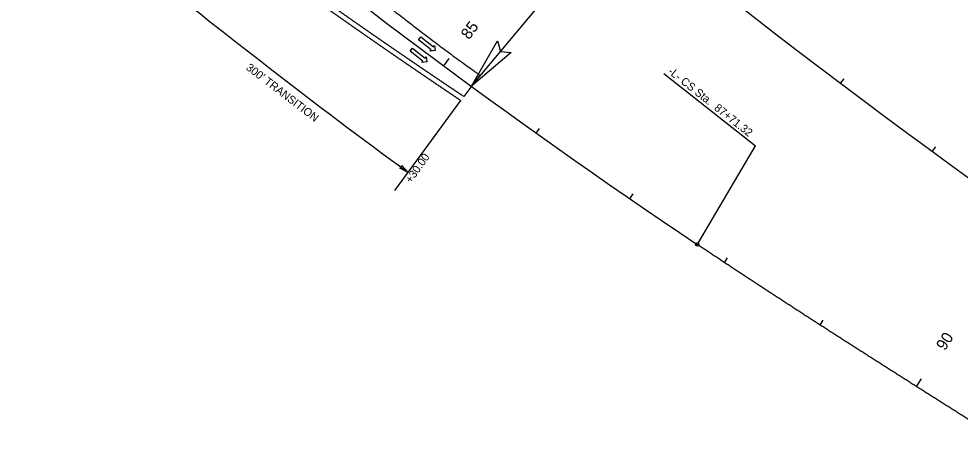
# Model space of a CAD drawing. Extents: x 1778969 to 1790720, y 807089 to 817794.
# Drawn here: x 1783038 to 1783861, y 811215 to 811575 of the extents above; entities that cross this region are included whole.
import ezdxf

# ---------------------------------------------------------------- set-up
doc = ezdxf.new("R2010")
doc.units = 0
for name, color, linetype in [('Prop Dimension', 7, 'Continuous'), ('Prop Dimension Text', 7, 'Continuous'), ('Prop EOT', 7, 'Continuous'), ('Prop Horizontal Alignment', 7, 'Continuous'), ('Prop Horizontal Alignment Station Label', 7, 'Continuous'), ('Prop Horizontal Alignment Tick Label', 7, 'Continuous'), ('Prop Horizontal Alignment Tick Large', 7, 'Continuous'), ('Prop Horizontal Alignment Tick Small', 7, 'Continuous'), ('Prop Lane Arrow CELL', 7, 'Continuous'), ('Prop Paved Shoulder', 7, 'Continuous'), ('Prop Terminator CELL', 7, 'Continuous')]:
    doc.layers.add(name, color=color, linetype=linetype)

msp = doc.modelspace()

# ---------------------------------------------------------------- linework, layer by layer
at = {"layer": 'Prop Dimension'}
msp.add_line((1783366.62, 811424.33), (1783424.41, 811503.2), dxfattribs=at)
msp.add_arc((1786819.89, 816137.48), 5823.1, 230.770165, 233.770165, dxfattribs=at)
at = {"layer": 'Prop EOT'}
msp.add_line((1783440.95, 811525.52), (1783427.01, 811506.75), dxfattribs=at)
msp.add_open_spline([(1782332.14, 812594.37), (1782340.74, 812583.67), (1782349.23, 812572.88), (1782357.82, 812562.17), (1782368.33, 812549.05), (1782378.92, 812535.99), (1782389.53, 812522.94), (1782400.47, 812509.49), (1782411.47, 812496.1), (1782422.5, 812482.73), (1782432.68, 812470.37), (1782442.88, 812458.04), (1782453.26, 812445.86), (1782464.11, 812433.14), (1782475.03, 812420.5), (1782485.99, 812407.88), (1782497.29, 812394.85), (1782508.62, 812381.84), (1782519.93, 812368.81), (1782530.42, 812356.73), (1782540.78, 812344.53), (1782551.36, 812332.52), (1782562.04, 812320.41), (1782573.16, 812308.69), (1782584.11, 812296.83), (1782595.68, 812284.29), (1782607.24, 812271.76), (1782618.83, 812259.26), (1782630.11, 812247.08), (1782641.41, 812234.93), (1782652.81, 812222.87), (1782664.21, 812210.82), (1782675.73, 812198.9), (1782687.17, 812186.89), (1782698.66, 812174.82), (1782710.02, 812162.63), (1782721.55, 812150.59), (1782732.97, 812138.66), (1782744.99, 812127.31), (1782756.58, 812115.53), (1782768.39, 812103.52), (1782779.79, 812091.1), (1782791.72, 812079.2), (1782803.99, 812066.97), (1782816.43, 812054.92), (1782828.91, 812042.91), (1782840.93, 812031.35), (1782852.92, 812019.75), (1782865.05, 812008.31), (1782876.51, 811997.51), (1782888.04, 811986.79), (1782899.51, 811976.02), (1782911.55, 811964.7), (1782923.49, 811953.28), (1782935.55, 811941.99), (1782948.31, 811930.06), (1782961.67, 811918.77), (1782974.58, 811907), (1782986.37, 811896.25), (1782997.7, 811885), (1783009.68, 811874.46), (1783022.12, 811863.52), (1783034.57, 811852.59), (1783047.02, 811841.66), (1783060.1, 811830.17), (1783073.18, 811818.66), (1783086.29, 811807.19), (1783098.84, 811796.2), (1783111.71, 811785.59), (1783124.49, 811774.86), (1783136.64, 811764.65), (1783148.81, 811754.45), (1783161, 811744.27), (1783173.76, 811733.61), (1783186.53, 811722.94), (1783199.48, 811712.51), (1783212.93, 811701.66), (1783226.61, 811691.1), (1783240.11, 811680.31), (1783252.73, 811670.21), (1783265.33, 811660.09), (1783277.95, 811649.99), (1783290.86, 811639.67), (1783303.73, 811629.3), (1783316.77, 811619.15), (1783330.23, 811608.67), (1783343.93, 811598.52), (1783357.48, 811588.16), (1783371.02, 811577.8), (1783384.46, 811567.3), (1783398.04, 811557), (1783410.94, 811547.2), (1783424.04, 811537.66), (1783437.2, 811528.21), (1783438.45, 811527.31), (1783439.7, 811526.42), (1783440.95, 811525.52)], degree=3, dxfattribs=at)
for points in [[(1783278.46, 811609.51), (1783279.12, 811609.03), (1783279.78, 811608.56), (1783280.44, 811608.09), (1783281.11, 811607.61), (1783281.77, 811607.14), (1783282.43, 811606.67), (1783283.09, 811606.19), (1783283.76, 811605.72), (1783284.42, 811605.25), (1783285.08, 811604.78), (1783285.75, 811604.3), (1783286.41, 811603.83), (1783287.07, 811603.36), (1783287.74, 811602.89), (1783288.4, 811602.41), (1783289.06, 811601.94), (1783289.72, 811601.47), (1783290.39, 811601), (1783291.05, 811600.52), (1783291.72, 811600.05), (1783292.38, 811599.58), (1783293.04, 811599.11), (1783293.71, 811598.64), (1783294.37, 811598.17), (1783295.03, 811597.7), (1783295.7, 811597.22), (1783296.36, 811596.75), (1783297.03, 811596.28), (1783297.69, 811595.81), (1783298.35, 811595.34), (1783299.02, 811594.87), (1783299.68, 811594.4), (1783300.35, 811593.93), (1783301.01, 811593.46), (1783301.68, 811592.99), (1783302.34, 811592.52), (1783303, 811592.05), (1783303.67, 811591.58), (1783304.33, 811591.11), (1783305, 811590.64), (1783305.66, 811590.17), (1783306.33, 811589.7), (1783306.99, 811589.23), (1783307.66, 811588.76), (1783308.32, 811588.29), (1783308.99, 811587.82), (1783309.65, 811587.35), (1783310.32, 811586.88), (1783310.98, 811586.41), (1783311.65, 811585.94), (1783312.31, 811585.48), (1783312.98, 811585.01), (1783313.65, 811584.54), (1783314.31, 811584.07), (1783314.98, 811583.6), (1783315.64, 811583.13), (1783316.31, 811582.66), (1783316.97, 811582.2), (1783317.64, 811581.73), (1783318.31, 811581.26), (1783318.97, 811580.79), (1783319.64, 811580.33), (1783320.3, 811579.86), (1783320.97, 811579.39), (1783321.64, 811578.92), (1783322.3, 811578.46), (1783322.97, 811577.99), (1783323.64, 811577.52), (1783324.3, 811577.05), (1783324.97, 811576.59), (1783325.64, 811576.12), (1783326.3, 811575.65), (1783326.97, 811575.19), (1783327.64, 811574.72)], [(1783327.64, 811574.72), (1783328.3, 811574.25), (1783328.97, 811573.79), (1783329.64, 811573.32), (1783330.3, 811572.86), (1783330.97, 811572.39), (1783331.64, 811571.92), (1783332.31, 811571.46), (1783332.97, 811570.99), (1783333.64, 811570.53), (1783334.31, 811570.06), (1783334.98, 811569.59), (1783335.64, 811569.13), (1783336.31, 811568.66), (1783336.98, 811568.2), (1783337.65, 811567.73), (1783338.31, 811567.27), (1783338.98, 811566.8), (1783339.65, 811566.34), (1783340.32, 811565.87), (1783340.99, 811565.41), (1783341.65, 811564.95), (1783342.32, 811564.48), (1783342.99, 811564.02), (1783343.66, 811563.55), (1783344.33, 811563.09), (1783345, 811562.62), (1783345.67, 811562.16), (1783346.33, 811561.7), (1783347, 811561.23), (1783347.67, 811560.77), (1783348.34, 811560.31), (1783349.01, 811559.84), (1783349.68, 811559.38), (1783350.35, 811558.92), (1783351.02, 811558.45), (1783351.68, 811557.99), (1783352.35, 811557.53), (1783353.02, 811557.06), (1783353.69, 811556.6), (1783354.36, 811556.14), (1783355.03, 811555.68), (1783355.7, 811555.21), (1783356.37, 811554.75), (1783357.04, 811554.29), (1783357.71, 811553.83), (1783358.38, 811553.36), (1783359.05, 811552.9), (1783359.72, 811552.44), (1783360.39, 811551.98), (1783361.06, 811551.52), (1783361.73, 811551.06), (1783362.4, 811550.59), (1783363.07, 811550.13), (1783363.74, 811549.67), (1783364.41, 811549.21), (1783365.08, 811548.75), (1783365.75, 811548.29), (1783366.42, 811547.83), (1783367.09, 811547.37), (1783367.76, 811546.91), (1783368.43, 811546.45), (1783369.1, 811545.98), (1783369.77, 811545.52), (1783370.44, 811545.06), (1783371.11, 811544.6), (1783371.79, 811544.14), (1783372.46, 811543.68), (1783373.13, 811543.22), (1783373.8, 811542.76), (1783374.47, 811542.3), (1783375.14, 811541.84), (1783375.81, 811541.39), (1783376.48, 811540.93), (1783377.16, 811540.47)], [(1783377.16, 811540.47), (1783377.83, 811540.01), (1783378.5, 811539.55), (1783379.17, 811539.09), (1783379.84, 811538.63), (1783380.51, 811538.17), (1783381.19, 811537.71), (1783381.86, 811537.25), (1783382.53, 811536.8), (1783383.2, 811536.34), (1783383.87, 811535.88), (1783384.55, 811535.42), (1783385.22, 811534.96), (1783385.89, 811534.5), (1783386.56, 811534.05), (1783387.23, 811533.59), (1783387.91, 811533.13), (1783388.58, 811532.67), (1783389.25, 811532.22), (1783389.92, 811531.76), (1783390.6, 811531.3), (1783391.27, 811530.84), (1783391.94, 811530.39), (1783392.61, 811529.93), (1783393.29, 811529.47), (1783393.96, 811529.02), (1783394.63, 811528.56), (1783395.31, 811528.1), (1783395.98, 811527.65), (1783396.65, 811527.19), (1783397.33, 811526.73), (1783398, 811526.28), (1783398.67, 811525.82), (1783399.35, 811525.36), (1783400.02, 811524.91), (1783400.69, 811524.45), (1783401.37, 811524), (1783402.04, 811523.54), (1783402.71, 811523.08), (1783403.39, 811522.63), (1783404.06, 811522.17), (1783404.74, 811521.72), (1783405.41, 811521.26), (1783406.08, 811520.81), (1783406.76, 811520.35), (1783407.43, 811519.9), (1783408.11, 811519.44), (1783408.78, 811518.99), (1783409.45, 811518.53), (1783410.13, 811518.08), (1783410.8, 811517.63), (1783411.48, 811517.17), (1783412.15, 811516.72), (1783412.83, 811516.26), (1783413.5, 811515.81), (1783414.18, 811515.35), (1783414.85, 811514.9), (1783415.53, 811514.45), (1783416.2, 811513.99), (1783416.88, 811513.54), (1783417.55, 811513.09), (1783418.23, 811512.63), (1783418.9, 811512.18), (1783419.58, 811511.73), (1783420.25, 811511.27), (1783420.93, 811510.82), (1783421.6, 811510.37), (1783422.28, 811509.92), (1783422.95, 811509.46), (1783423.63, 811509.01), (1783424.31, 811508.56), (1783424.98, 811508.11), (1783425.66, 811507.65), (1783427.01, 811506.75)]]:
    msp.add_spline(points, degree=3, dxfattribs=at)
at = {"layer": 'Prop Horizontal Alignment'}
for centre, radius, start, end in [((1788355.99, 817618.07), 7639.44, 213.341667, 236.008333), ((1786819.89, 816137.48), 5729.58, 212.5, 236.18333)]:
    msp.add_arc(centre, radius, start, end, dxfattribs=at)
msp.add_spline([(1783883.28, 811214.63), (1783879.86, 811216.8), (1783876.43, 811218.97), (1783873.01, 811221.14), (1783869.58, 811223.3), (1783866.15, 811225.47), (1783862.73, 811227.64), (1783859.3, 811229.81), (1783855.88, 811231.97), (1783852.45, 811234.14), (1783849.03, 811236.31), (1783845.6, 811238.48), (1783842.18, 811240.65), (1783838.75, 811242.82), (1783835.33, 811244.99), (1783831.9, 811247.16), (1783828.48, 811249.33), (1783825.06, 811251.5), (1783821.64, 811253.68), (1783818.21, 811255.85), (1783814.79, 811258.02), (1783811.37, 811260.2), (1783807.95, 811262.37), (1783804.53, 811264.55), (1783801.11, 811266.72), (1783797.69, 811268.9), (1783794.27, 811271.08), (1783790.85, 811273.26), (1783787.43, 811275.44), (1783784.01, 811277.62), (1783780.6, 811279.8), (1783777.18, 811281.98), (1783773.76, 811284.17), (1783770.35, 811286.35), (1783766.93, 811288.54), (1783763.52, 811290.72), (1783760.11, 811292.91), (1783756.69, 811295.1), (1783753.28, 811297.29), (1783749.87, 811299.48), (1783746.46, 811301.67), (1783743.05, 811303.87), (1783739.65, 811306.06), (1783736.24, 811308.26), (1783732.83, 811310.46), (1783729.43, 811312.66), (1783726.02, 811314.86), (1783722.62, 811317.06), (1783719.22, 811319.27), (1783715.81, 811321.47), (1783712.41, 811323.68), (1783709.01, 811325.89), (1783705.62, 811328.1), (1783702.22, 811330.31), (1783698.82, 811332.52), (1783695.43, 811334.74), (1783692.03, 811336.96), (1783688.64, 811339.18), (1783685.25, 811341.4), (1783681.86, 811343.62), (1783678.47, 811345.85), (1783675.08, 811348.07), (1783671.7, 811350.3), (1783668.31, 811352.53), (1783664.93, 811354.77), (1783661.55, 811357), (1783658.16, 811359.24), (1783654.78, 811361.48), (1783651.41, 811363.72), (1783648.03, 811365.96), (1783644.66, 811368.21), (1783641.28, 811370.46), (1783637.91, 811372.71), (1783634.54, 811374.96), (1783631.17, 811377.21)], degree=3, dxfattribs=at)
at = {"layer": 'Prop Horizontal Alignment Station Label'}
for p, q in [((1783433.57, 811515.7), (1783492.61, 811586.17)), ((1783601.88, 811526.98), (1783682.13, 811463.45)), ((1783632, 811378.46), (1783682.13, 811463.45))]:
    msp.add_line(p, q, dxfattribs=at)
msp.add_circle((1783631.17, 811377.21), 1.5, dxfattribs=at)
at = {"layer": 'Prop Horizontal Alignment Tick Large'}
for p, q in [((1783409.41, 811533.49), (1783414.17, 811539.92)), ((1783823.03, 811252.79), (1783827.32, 811259.54))]:
    msp.add_line(p, q, dxfattribs=at)
at = {"layer": 'Prop Horizontal Alignment Tick Small'}
for p, q in [((1783756.64, 811518.32), (1783759.65, 811522.32)), ((1783490.28, 811474.67), (1783493.19, 811478.74)), ((1783836.87, 811458.64), (1783839.83, 811462.67)), ((1783572.17, 811417.27), (1783575, 811421.39)), ((1783655.04, 811361.31), (1783657.8, 811365.48)), ((1783738.77, 811306.63), (1783741.47, 811310.83))]:
    msp.add_line(p, q, dxfattribs=at)
at = {"layer": 'Prop Lane Arrow CELL'}
for p, q in [((1783387.3, 811556.29), (1783389.35, 811558.88)), ((1783398.27, 811547.6), (1783387.3, 811556.29)), ((1783389.35, 811558.88), (1783400.32, 811550.19)), ((1783380.07, 811546.31), (1783382.12, 811548.9)), ((1783391.04, 811537.62), (1783380.07, 811546.31)), ((1783382.12, 811548.9), (1783393.09, 811540.21)), ((1783397.34, 811546.42), (1783398.27, 811547.6)), ((1783401.8, 811546.98), (1783397.34, 811546.42)), ((1783400.32, 811550.19), (1783401.25, 811551.36)), ((1783401.25, 811551.36), (1783401.8, 811546.98)), ((1783390.11, 811536.45), (1783391.04, 811537.62)), ((1783393.09, 811540.21), (1783394.02, 811541.39)), ((1783394.02, 811541.39), (1783394.57, 811537)), ((1783394.57, 811537), (1783390.11, 811536.45))]:
    msp.add_line(p, q, dxfattribs=at)
at = {"layer": 'Prop Paved Shoulder'}
for points in [[(1783275.89, 811606.23), (1783276.56, 811605.76), (1783277.22, 811605.28), (1783277.88, 811604.81), (1783278.54, 811604.33), (1783279.21, 811603.86), (1783279.87, 811603.38), (1783280.53, 811602.91), (1783281.19, 811602.43), (1783281.86, 811601.96), (1783282.52, 811601.49), (1783283.18, 811601.01), (1783283.84, 811600.54), (1783284.51, 811600.06), (1783285.17, 811599.59), (1783285.83, 811599.12), (1783286.5, 811598.64), (1783287.16, 811598.17), (1783287.82, 811597.7), (1783288.48, 811597.22), (1783289.15, 811596.75), (1783289.81, 811596.28), (1783290.47, 811595.81), (1783291.14, 811595.33), (1783291.8, 811594.86), (1783292.47, 811594.39), (1783293.13, 811593.92), (1783293.79, 811593.44), (1783294.46, 811592.97), (1783295.12, 811592.5), (1783295.78, 811592.03), (1783296.45, 811591.55), (1783297.11, 811591.08), (1783297.78, 811590.61), (1783298.44, 811590.14), (1783299.1, 811589.67), (1783299.77, 811589.2), (1783300.43, 811588.72), (1783301.1, 811588.25), (1783301.76, 811587.78), (1783302.43, 811587.31), (1783303.09, 811586.84), (1783303.76, 811586.37), (1783304.42, 811585.9), (1783305.09, 811585.43), (1783305.75, 811584.96), (1783306.42, 811584.49), (1783307.08, 811584.02), (1783307.75, 811583.55), (1783308.41, 811583.08), (1783309.08, 811582.61), (1783309.74, 811582.14), (1783310.41, 811581.67), (1783311.07, 811581.2), (1783311.74, 811580.73), (1783312.4, 811580.26), (1783313.07, 811579.79), (1783313.73, 811579.32), (1783314.4, 811578.85), (1783315.07, 811578.38), (1783315.73, 811577.91), (1783316.4, 811577.44), (1783317.06, 811576.97), (1783317.73, 811576.5), (1783318.39, 811576.03), (1783319.06, 811575.57), (1783319.73, 811575.1), (1783320.39, 811574.63), (1783321.06, 811574.16), (1783321.73, 811573.69), (1783322.39, 811573.22), (1783323.06, 811572.76), (1783323.73, 811572.29), (1783324.39, 811571.82), (1783325.06, 811571.35)], [(1783325.06, 811571.35), (1783325.73, 811570.88), (1783326.39, 811570.42), (1783327.06, 811569.95), (1783327.73, 811569.48), (1783328.39, 811569.01), (1783329.06, 811568.55), (1783329.73, 811568.08), (1783330.39, 811567.61), (1783331.06, 811567.15), (1783331.73, 811566.68), (1783332.4, 811566.21), (1783333.06, 811565.75), (1783333.73, 811565.28), (1783334.4, 811564.81), (1783335.07, 811564.35), (1783335.73, 811563.88), (1783336.4, 811563.42), (1783337.07, 811562.95), (1783337.74, 811562.48), (1783338.41, 811562.02), (1783339.07, 811561.55), (1783339.74, 811561.09), (1783340.41, 811560.62), (1783341.08, 811560.15), (1783341.75, 811559.69), (1783342.41, 811559.22), (1783343.08, 811558.76), (1783343.75, 811558.29), (1783344.42, 811557.83), (1783345.09, 811557.36), (1783345.76, 811556.9), (1783346.43, 811556.43), (1783347.09, 811555.97), (1783347.76, 811555.51), (1783348.43, 811555.04), (1783349.1, 811554.58), (1783349.77, 811554.11), (1783350.44, 811553.65), (1783351.11, 811553.18), (1783351.78, 811552.72), (1783352.45, 811552.26), (1783353.12, 811551.79), (1783353.78, 811551.33), (1783354.45, 811550.87), (1783355.12, 811550.4), (1783355.79, 811549.94), (1783356.46, 811549.48), (1783357.13, 811549.01), (1783357.8, 811548.55), (1783358.47, 811548.09), (1783359.14, 811547.62), (1783359.81, 811547.16), (1783360.48, 811546.7), (1783361.15, 811546.24), (1783361.82, 811545.77), (1783362.49, 811545.31), (1783363.16, 811544.85), (1783363.83, 811544.39), (1783364.5, 811543.93), (1783365.17, 811543.46), (1783365.84, 811543), (1783366.51, 811542.54), (1783367.18, 811542.08), (1783367.86, 811541.62), (1783368.53, 811541.16), (1783369.2, 811540.69), (1783369.87, 811540.23), (1783370.54, 811539.77), (1783371.21, 811539.31), (1783371.88, 811538.85), (1783372.55, 811538.39), (1783373.22, 811537.93), (1783373.89, 811537.47), (1783374.56, 811537.01)], [(1783374.56, 811537.01), (1783375.24, 811536.55), (1783375.91, 811536.09), (1783376.58, 811535.63), (1783377.25, 811535.17), (1783377.92, 811534.71), (1783378.59, 811534.25), (1783379.27, 811533.79), (1783379.94, 811533.33), (1783380.61, 811532.87), (1783381.28, 811532.41), (1783381.95, 811531.95), (1783382.62, 811531.49), (1783383.3, 811531.03), (1783383.97, 811530.57), (1783384.64, 811530.11), (1783385.31, 811529.65), (1783385.99, 811529.19), (1783386.66, 811528.73), (1783387.33, 811528.28), (1783388, 811527.82), (1783388.68, 811527.36), (1783389.35, 811526.9), (1783390.02, 811526.44), (1783390.69, 811525.98), (1783391.37, 811525.53), (1783392.04, 811525.07), (1783392.71, 811524.61), (1783393.38, 811524.15), (1783394.06, 811523.69), (1783394.73, 811523.24), (1783395.4, 811522.78), (1783396.08, 811522.32), (1783396.75, 811521.86), (1783397.42, 811521.41), (1783398.1, 811520.95), (1783398.77, 811520.49), (1783399.44, 811520.04), (1783400.12, 811519.58), (1783400.79, 811519.12), (1783401.47, 811518.67), (1783402.14, 811518.21), (1783402.81, 811517.75), (1783403.49, 811517.3), (1783404.16, 811516.84), (1783404.83, 811516.38), (1783405.51, 811515.93), (1783406.18, 811515.47), (1783406.86, 811515.02), (1783407.53, 811514.56), (1783408.21, 811514.1), (1783408.88, 811513.65), (1783409.55, 811513.19), (1783410.23, 811512.74), (1783410.9, 811512.28), (1783411.58, 811511.83), (1783412.25, 811511.37), (1783412.93, 811510.92), (1783413.6, 811510.46), (1783414.28, 811510.01), (1783414.95, 811509.55), (1783415.63, 811509.1), (1783416.3, 811508.64), (1783416.98, 811508.19), (1783417.65, 811507.74), (1783418.33, 811507.28), (1783419, 811506.83), (1783419.68, 811506.37), (1783420.35, 811505.92), (1783421.03, 811505.47), (1783421.7, 811505.01), (1783422.38, 811504.56), (1783423.06, 811504.1), (1783424.41, 811503.2)]]:
    msp.add_spline(points, degree=3, dxfattribs=at)
at = {"layer": 'Prop Terminator CELL'}
for points in [[(1783468.41, 811545.21), (1783433.57, 811515.7), (1783456.49, 811555.52), (1783458.93, 811545.97)], [(1783372.59, 811446.18), (1783378.29, 811440.26), (1783370.87, 811443.92), (1783372.56, 811444.47)]]:
    msp.add_lwpolyline(points, close=True, dxfattribs=at)

# ---------------------------------------------------------------- texts
at = {"layer": 'Prop Dimension Text'}
for s, rotation, p in [("300' TRANSITION", 322.4989, (1783235.8, 811530.78)), ('+30.00', 54.49702, (1783380.72, 811430.25))]:
    msp.add_text(s, height=7, rotation=rotation, dxfattribs=at).set_placement(p)
at = {"layer": 'Prop Horizontal Alignment Station Label'}
msp.add_text('-L- CS Sta.  87+71.32', height=7, rotation=321.57046, dxfattribs=at).set_placement((1783605.05, 811527.55))
at = {"layer": 'Prop Horizontal Alignment Tick Label'}
for s, rotation, p in [('85', 53.47016, (1783431.56, 811555.9)), ('90', 57.59857, (1783847.92, 811283.64))]:
    msp.add_text(s, height=10, rotation=rotation, dxfattribs=at).set_placement(p)

doc.saveas('drawing.dxf')
